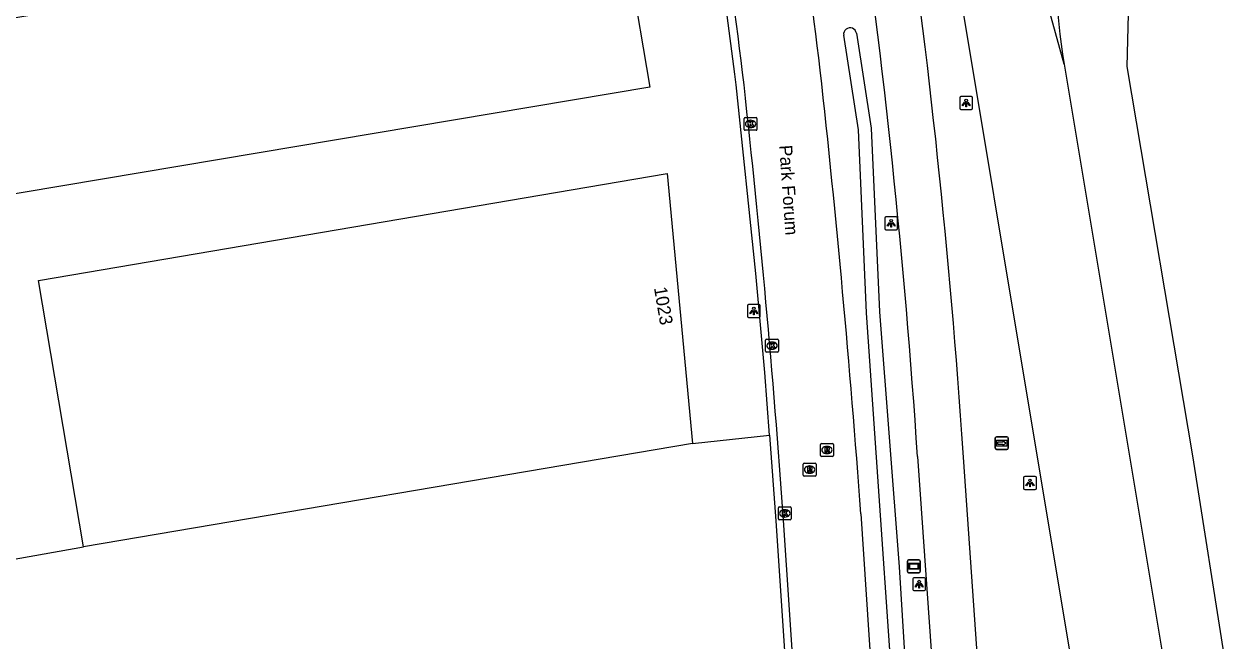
# Model space of a CAD drawing. Extents: x 154324 to 155743, y 382939 to 384183.
# Drawn here: x 155008 to 155101.4, y 383380.6 to 383428.3 of the extents above; entities that cross this region are included whole.
import ezdxf

# ---------------------------------------------------------------- set-up
doc = ezdxf.new("R2010")
doc.units = 0
for name, color, linetype in [('IMGEO_Fietspad_gesloten', 7, 'Continuous'), ('IMGEO_Grasland_agrarisch', 7, 'Continuous'), ('IMGEO_Greppel_droge_sloot', 7, 'Continuous'), ('IMGEO_Kolk', 7, 'Continuous'), ('IMGEO_Lichtpunt', 7, 'Continuous'), ('IMGEO_Loofbos', 7, 'Continuous'), ('IMGEO_Openbare_ruimte_label', 7, 'Continuous'), ('IMGEO_Pand', 7, 'Continuous'), ('IMGEO_Pand_nummerreeks', 7, 'Continuous'), ('IMGEO_Rijbaan_lokaal_gesloten', 7, 'Continuous'), ('IMGEO_Rijbaan_lokaal_open', 7, 'Continuous'), ('IMGEO_Rijbaan_regionaal_gesloten', 7, 'Continuous'), ('IMGEO_Rioolput', 7, 'Continuous'), ('IMGEO_Verklikker', 7, 'Continuous'), ('IMGEO_Wegwijzer', 7, 'Continuous')]:
    doc.layers.add(name, color=color, linetype=linetype)

msp = doc.modelspace()

# ---------------------------------------------------------------- linework, layer by layer
at = {"layer": 'IMGEO_Fietspad_gesloten'}
for points in [[(155077.17, 383394.842), (155080.905, 383341.835), (155081.566, 383327.494), (155081.827, 383312.283), (155081.9, 383290.584)], [(155085.135, 383323.941), (155085.067, 383327.696), (155084.447, 383341.596), (155080.698, 383395.149)]]:
    msp.add_lwpolyline(points, dxfattribs=at)
for centre, radius, start, end in [((154487.454, 383355.336), 594.578, 3.839363, 8.252921), ((154487.732, 383355.709), 590.736, 3.798282, 8.215646)]:
    msp.add_arc(centre, radius, start, end, dxfattribs=at)
at = {"layer": 'IMGEO_Grasland_agrarisch'}
for points in [[(154989.658, 383412.19), (154994.323, 383384.618), (155012.632, 383387.85)], [(155059.756, 383395.855), (155065.709, 383396.485)]]:
    msp.add_lwpolyline(points, dxfattribs=at)
at = {"layer": 'IMGEO_Greppel_droge_sloot'}
for points in [[(155076.041, 383365.341), (155073.219, 383405.951), (155072.594, 383420.096), (155071.455, 383427.398)], [(155072.443, 383427.552), (155073.586, 383420.223), (155074.216, 383406.02)], [(155074.216, 383406.02), (155075.741, 383386.313), (155077.04, 383365.403)]]:
    msp.add_lwpolyline(points, dxfattribs=at)
msp.add_arc((155071.949, 383427.475), 0.5, 8.85254, 188.86632, dxfattribs=at)
at = {"layer": 'IMGEO_Kolk'}
for p, q in [((155063.742, 383420.127), (155063.742, 383420.979)), ((155063.817, 383421.053), (155064.669, 383421.053)), ((155064.23, 383420.833), (155064.255, 383420.833)), ((155064.743, 383420.979), (155064.743, 383420.127)), ((155064.669, 383420.053), (155063.817, 383420.053)), ((155064.253, 383420.273), (155064.228, 383420.273)), ((155065.406, 383402.98), (155065.406, 383403.832)), ((155065.481, 383403.906), (155066.333, 383403.906)), ((155066.407, 383403.832), (155066.407, 383402.98)), ((155066.333, 383402.906), (155065.481, 383402.906)), ((155065.917, 383403.126), (155065.892, 383403.126)), ((155065.894, 383403.686), (155065.919, 383403.686)), ((155066.397, 383390.012), (155066.397, 383390.864)), ((155066.472, 383390.938), (155067.324, 383390.938)), ((155066.885, 383390.718), (155066.91, 383390.718)), ((155067.398, 383390.864), (155067.398, 383390.012)), ((155067.324, 383389.938), (155066.472, 383389.938)), ((155066.908, 383390.158), (155066.883, 383390.158))]:
    msp.add_line(p, q, dxfattribs=at)
for points in [[(155063.742, 383420.127), (155063.742, 383420.979)], [(155063.817, 383421.053), (155064.669, 383421.053)], [(155064.063, 383420.753), (155064.186, 383420.753), (155064.186, 383420.602), (155064.316, 383420.753), (155064.48, 383420.753), (155064.334, 383420.602), (155064.487, 383420.353), (155064.335, 383420.353), (155064.25, 383420.517), (155064.186, 383420.45), (155064.186, 383420.353), (155064.063, 383420.353), (155064.063, 383420.753)], [(155064.743, 383420.979), (155064.743, 383420.127)], [(155064.669, 383420.053), (155063.817, 383420.053)], [(155065.406, 383402.98), (155065.406, 383403.832)], [(155065.481, 383403.906), (155066.333, 383403.906)], [(155066.407, 383403.832), (155066.407, 383402.98)], [(155066.333, 383402.906), (155065.481, 383402.906)], [(155065.727, 383403.606), (155065.85, 383403.606), (155065.85, 383403.455), (155065.98, 383403.606), (155066.144, 383403.606), (155065.998, 383403.455), (155066.151, 383403.206), (155065.999, 383403.206), (155065.914, 383403.37), (155065.85, 383403.303), (155065.85, 383403.206), (155065.727, 383403.206), (155065.727, 383403.606)], [(155066.397, 383390.012), (155066.397, 383390.864)], [(155066.472, 383390.938), (155067.324, 383390.938)], [(155067.398, 383390.864), (155067.398, 383390.012)], [(155067.324, 383389.938), (155066.472, 383389.938)], [(155066.718, 383390.638), (155066.841, 383390.638), (155066.841, 383390.487), (155066.971, 383390.638), (155067.135, 383390.638), (155066.989, 383390.487), (155067.142, 383390.238), (155066.99, 383390.238), (155066.905, 383390.402), (155066.841, 383390.335), (155066.841, 383390.238), (155066.718, 383390.238), (155066.718, 383390.638)]]:
    msp.add_lwpolyline(points, dxfattribs=at)
for centre, start, end in [((155063.819, 383420.977), 91.55205, 178.44795), ((155063.819, 383420.977), 91.55205, 178.44795), ((155064.667, 383420.977), 1.55205, 88.44795), ((155064.667, 383420.977), 1.55205, 88.44795), ((155063.819, 383420.129), 181.55205, 268.44795), ((155063.819, 383420.129), 181.55205, 268.44795), ((155064.667, 383420.129), 271.55205, 358.44795), ((155064.667, 383420.129), 271.55205, 358.44795), ((155065.483, 383403.83), 91.55205, 178.44795), ((155065.483, 383403.83), 91.55205, 178.44795), ((155066.331, 383403.83), 1.55205, 88.44795), ((155066.331, 383403.83), 1.55205, 88.44795), ((155065.483, 383402.982), 181.55205, 268.44795), ((155065.483, 383402.982), 181.55205, 268.44795), ((155066.331, 383402.982), 271.55205, 358.44795), ((155066.331, 383402.982), 271.55205, 358.44795), ((155066.474, 383390.862), 91.55205, 178.44795), ((155066.474, 383390.862), 91.55205, 178.44795), ((155067.322, 383390.862), 1.55205, 88.44795), ((155067.322, 383390.862), 1.55205, 88.44795), ((155066.474, 383390.014), 181.55205, 268.44795), ((155066.474, 383390.014), 181.55205, 268.44795), ((155067.322, 383390.014), 271.55205, 358.44795), ((155067.322, 383390.014), 271.55205, 358.44795)]:
    msp.add_arc(centre, 0.0765, start, end, dxfattribs=at)
for centre, major_axis, ratio, start_param, end_param in [((155064.229, 383420.553), (-0.387, 0.002), 0.722429, 4.712389, 7.853982), ((155064.254, 383420.553), (-0.39, 0.002), 0.717154, 1.570796, 4.712389), ((155065.893, 383403.406), (-0.387, 0.002), 0.722429, 4.712389, 7.853982), ((155065.918, 383403.406), (-0.39, 0.002), 0.717154, 1.570796, 4.712389), ((155066.884, 383390.438), (-0.387, 0.002), 0.722429, 4.712389, 7.853982), ((155066.909, 383390.438), (-0.39, 0.002), 0.717154, 1.570796, 4.712389)]:
    msp.add_ellipse(centre, major_axis=major_axis, ratio=ratio, start_param=start_param, end_param=end_param, dxfattribs=at)
at = {"layer": 'IMGEO_Lichtpunt'}
for p, q in [((155080.434, 383422.566), (155080.434, 383421.759)), ((155080.434, 383422.566), (155080.434, 383421.759)), ((155081.336, 383422.661), (155080.528, 383422.661)), ((155081.336, 383422.661), (155080.528, 383422.661)), ((155081.43, 383421.759), (155081.43, 383422.566)), ((155081.43, 383421.759), (155081.43, 383422.566)), ((155080.528, 383421.665), (155081.336, 383421.665)), ((155080.528, 383421.665), (155081.336, 383421.665)), ((155074.633, 383413.273), (155074.633, 383412.466)), ((155074.633, 383413.273), (155074.633, 383412.466)), ((155075.535, 383413.368), (155074.727, 383413.368)), ((155075.535, 383413.368), (155074.727, 383413.368)), ((155075.629, 383412.466), (155075.629, 383413.273)), ((155075.629, 383412.466), (155075.629, 383413.273)), ((155074.727, 383412.372), (155075.535, 383412.372)), ((155074.727, 383412.372), (155075.535, 383412.372)), ((155064.902, 383406.59), (155064.094, 383406.59)), ((155064.902, 383406.59), (155064.094, 383406.59)), ((155064, 383406.495), (155064, 383405.688)), ((155064, 383406.495), (155064, 383405.688)), ((155064.094, 383405.594), (155064.902, 383405.594)), ((155064.094, 383405.594), (155064.902, 383405.594)), ((155064.996, 383405.688), (155064.996, 383406.495)), ((155064.996, 383405.688), (155064.996, 383406.495)), ((155085.373, 383393.191), (155085.373, 383392.384)), ((155085.373, 383393.191), (155085.373, 383392.384)), ((155086.275, 383393.286), (155085.467, 383393.286)), ((155086.275, 383393.286), (155085.467, 383393.286)), ((155086.369, 383392.384), (155086.369, 383393.191)), ((155086.369, 383392.384), (155086.369, 383393.191)), ((155085.467, 383392.29), (155086.275, 383392.29)), ((155085.467, 383392.29), (155086.275, 383392.29)), ((155076.799, 383385.371), (155076.799, 383384.564)), ((155076.799, 383385.371), (155076.799, 383384.564)), ((155077.701, 383385.466), (155076.893, 383385.466)), ((155077.701, 383385.466), (155076.893, 383385.466)), ((155077.795, 383384.564), (155077.795, 383385.371)), ((155077.795, 383384.564), (155077.795, 383385.371)), ((155076.893, 383384.47), (155077.701, 383384.47)), ((155076.893, 383384.47), (155077.701, 383384.47))]:
    msp.add_line(p, q, dxfattribs=at)
for points in [[(155080.808, 383422.23), (155080.847, 383422.202), (155080.659, 383421.94), (155080.621, 383421.967), (155080.808, 383422.23)], [(155080.91, 383422.182), (155080.957, 383422.182), (155080.957, 383421.86), (155080.91, 383421.86), (155080.91, 383422.182)], [(155081.02, 383422.202), (155081.058, 383422.229), (155081.245, 383421.967), (155081.206, 383421.939), (155081.02, 383422.202)], [(155075.007, 383412.937), (155075.046, 383412.909), (155074.858, 383412.647), (155074.82, 383412.674), (155075.007, 383412.937)], [(155075.109, 383412.889), (155075.156, 383412.889), (155075.156, 383412.567), (155075.109, 383412.567), (155075.109, 383412.889)], [(155075.219, 383412.909), (155075.257, 383412.936), (155075.444, 383412.674), (155075.405, 383412.646), (155075.219, 383412.909)], [(155064.374, 383406.159), (155064.413, 383406.131), (155064.225, 383405.869), (155064.187, 383405.896), (155064.374, 383406.159)], [(155064.476, 383406.111), (155064.523, 383406.111), (155064.523, 383405.789), (155064.476, 383405.789), (155064.476, 383406.111)], [(155064.586, 383406.131), (155064.624, 383406.158), (155064.811, 383405.896), (155064.772, 383405.868), (155064.586, 383406.131)], [(155085.747, 383392.855), (155085.786, 383392.827), (155085.598, 383392.565), (155085.56, 383392.592), (155085.747, 383392.855)], [(155085.849, 383392.807), (155085.896, 383392.807), (155085.896, 383392.485), (155085.849, 383392.485), (155085.849, 383392.807)], [(155085.959, 383392.827), (155085.997, 383392.854), (155086.184, 383392.592), (155086.145, 383392.564), (155085.959, 383392.827)], [(155077.173, 383385.035), (155077.212, 383385.007), (155077.024, 383384.745), (155076.986, 383384.772), (155077.173, 383385.035)], [(155077.275, 383384.987), (155077.322, 383384.987), (155077.322, 383384.665), (155077.275, 383384.665), (155077.275, 383384.987)], [(155077.385, 383385.007), (155077.423, 383385.034), (155077.61, 383384.772), (155077.571, 383384.744), (155077.385, 383385.007)]]:
    msp.add_lwpolyline(points, dxfattribs=at)
for centre in [(155080.933, 383422.364), (155075.132, 383413.071), (155064.499, 383406.293), (155085.872, 383392.989), (155077.298, 383385.169)]:
    msp.add_circle(centre, 0.0994, dxfattribs=at)
for centre, start, end in [((155080.528, 383422.566), 90, 180), ((155080.528, 383422.566), 90, 180), ((155081.336, 383422.566), 0, 90), ((155081.336, 383422.566), 0, 90), ((155080.528, 383421.759), 180, 270), ((155080.528, 383421.759), 180, 270), ((155081.336, 383421.759), 270, 0), ((155081.336, 383421.759), 270, 360), ((155074.727, 383413.273), 90, 180), ((155074.727, 383413.273), 90, 180), ((155075.535, 383413.273), 0, 90), ((155075.535, 383413.273), 0, 90), ((155074.727, 383412.466), 180, 270), ((155074.727, 383412.466), 180, 270), ((155075.535, 383412.466), 270, 0), ((155075.535, 383412.466), 270, 360), ((155064.094, 383406.495), 90, 180), ((155064.094, 383406.495), 90, 180), ((155064.902, 383406.495), 0, 90), ((155064.902, 383406.495), 0, 90), ((155064.094, 383405.688), 180, 270), ((155064.094, 383405.688), 180, 270), ((155064.902, 383405.688), 270, 0), ((155064.902, 383405.688), 270, 360), ((155085.467, 383393.191), 90, 180), ((155085.467, 383393.191), 90, 180), ((155086.275, 383393.191), 0, 90), ((155086.275, 383393.191), 0, 90), ((155085.467, 383392.384), 180, 270), ((155085.467, 383392.384), 180, 270), ((155086.275, 383392.384), 270, 0), ((155086.275, 383392.384), 270, 360), ((155076.893, 383385.371), 90, 180), ((155076.893, 383385.371), 90, 180), ((155077.701, 383385.371), 0, 90), ((155077.701, 383385.371), 0, 90), ((155076.893, 383384.564), 180, 270), ((155076.893, 383384.564), 180, 270), ((155077.701, 383384.564), 270, 0), ((155077.701, 383384.564), 270, 360)]:
    msp.add_arc(centre, 0.0946, start, end, dxfattribs=at)
at = {"layer": 'IMGEO_Loofbos'}
msp.add_lwpolyline([(155098.468, 383394.88), (155093.402, 383424.985), (155093.91, 383445.3), (155100.943, 383462.488), (155107.736, 383471.089), (155129.143, 383483.74), (155137.144, 383484.281), (155140.63, 383467.071), (155136.381, 383463.412), (155137.911, 383457.313), (155135.315, 383439.71), (155145.951, 383434.989), (155156.14, 383427.969), (155169.731, 383420.841), (155156.553, 383398.835), (155144.405, 383376.88), (155136.829, 383369.749), (155130.45, 383360.745), (155130.039, 383352.225), (155124.389, 383342.473), (155103.488, 383363.139), (155098.468, 383394.88)], dxfattribs=at)
at = {"layer": 'IMGEO_Pand'}
for points in [[(154987.442, 383425.439), (155016.017, 383430.255), (155015.086, 383435.797), (155040.407, 383440.106), (155045.605, 383440.97), (155045.151, 383443.703), (155044.599, 383443.611), (155044.545, 383443.936), (155052.777, 383445.305), (155054.28, 383436.31), (155053.008, 383436.097), (155053.665, 383432.17), (155054.937, 383432.384), (155056.445, 383423.395), (154989.658, 383412.19)], [(155012.632, 383387.85), (155009.132, 383408.441), (155057.795, 383416.713), (155059.756, 383395.855)], [(155059.756, 383395.855), (155012.632, 383387.85)]]:
    msp.add_lwpolyline(points, dxfattribs=at)
at = {"layer": 'IMGEO_Rijbaan_lokaal_gesloten'}
for points in [[(155070.546, 383334.082), (155066.805, 383389.917)], [(155072.788, 383390.399), (155076.503, 383334.279)]]:
    msp.add_lwpolyline(points, dxfattribs=at)
for centre, radius, start, end in [((154416.191, 383345.471), 658.237, 6.914298, 9.527814), ((154372.74, 383339.354), 696.116, 6.949521, 9.434678), ((154136.569, 383321.838), 938.726, 4.1884, 6.291685), ((154201.434, 383328.122), 867.574, 4.08448, 6.316961)]:
    msp.add_arc(centre, radius, start, end, dxfattribs=at)
at = {"layer": 'IMGEO_Rijbaan_lokaal_open'}
for points in [[(155065.709, 383396.485), (155065.341, 383401.33), (155064.659, 383408.986), (155063.139, 383423.564), (155063.03, 383424.403), (155061.613, 383435.27), (155060.487, 383443.041), (155058.846, 383453.397), (155045.918, 383530.449), (155024.164, 383660.104), (155016.277, 383707.107)], [(155065.709, 383396.485), (155066.213, 383389.857), (155069.432, 383341.538), (155069.458, 383341.15)]]:
    msp.add_lwpolyline(points, dxfattribs=at)
at = {"layer": 'IMGEO_Rijbaan_regionaal_gesloten'}
for points in [[(155071.187, 383485.369), (155076.819, 383452.367), (155095.519, 383340.332), (155097.848, 383325.634)], [(155088.506, 383425.158), (155082.147, 383448.215)], [(155088.506, 383425.158), (155097.016, 383374.301)]]:
    msp.add_lwpolyline(points, dxfattribs=at)
msp.add_arc((155150.9, 383434.774), 63.13, 166.13008, 188.76182, dxfattribs=at)
at = {"layer": 'IMGEO_Rioolput'}
for p, q in [((155069.656, 383394.918), (155069.656, 383395.77)), ((155069.731, 383395.844), (155070.583, 383395.844)), ((155070.144, 383395.624), (155070.169, 383395.624)), ((155070.657, 383395.77), (155070.657, 383394.918)), ((155070.583, 383394.844), (155069.731, 383394.844)), ((155070.167, 383395.064), (155070.142, 383395.064)), ((155068.313, 383393.402), (155068.313, 383394.254)), ((155068.388, 383394.328), (155069.24, 383394.328)), ((155068.824, 383393.548), (155068.799, 383393.548)), ((155068.801, 383394.108), (155068.826, 383394.108)), ((155069.314, 383394.254), (155069.314, 383393.402)), ((155069.24, 383393.328), (155068.388, 383393.328))]:
    msp.add_line(p, q, dxfattribs=at)
for points in [[(155069.656, 383394.918), (155069.656, 383395.77)], [(155069.731, 383395.844), (155070.583, 383395.844)], [(155070.245, 383395.542), (155069.993, 383395.544), (155069.993, 383395.144)], [(155070.171, 383395.463), (155070.117, 383395.463), (155070.117, 383395.382)], [(155070.117, 383395.382), (155070.169, 383395.382)], [(155070.657, 383395.77), (155070.657, 383394.918)], [(155070.583, 383394.844), (155069.731, 383394.844)], [(155069.993, 383395.144), (155070.117, 383395.144), (155070.117, 383395.306), (155070.128, 383395.306)], [(155070.175, 383395.277), (155070.246, 383395.144), (155070.386, 383395.144), (155070.321, 383395.27)], [(155068.313, 383393.402), (155068.313, 383394.254)], [(155068.388, 383394.328), (155069.24, 383394.328)], [(155068.902, 383394.026), (155068.65, 383394.028), (155068.65, 383393.628)], [(155068.65, 383393.628), (155068.774, 383393.628), (155068.774, 383393.79), (155068.785, 383393.79)], [(155068.828, 383393.947), (155068.774, 383393.947), (155068.774, 383393.866)], [(155068.774, 383393.866), (155068.826, 383393.866)], [(155068.832, 383393.761), (155068.903, 383393.628), (155069.043, 383393.628), (155068.978, 383393.754)], [(155069.314, 383394.254), (155069.314, 383393.402)], [(155069.24, 383393.328), (155068.388, 383393.328)]]:
    msp.add_lwpolyline(points, dxfattribs=at)
for centre, radius, start, end in [((155069.733, 383395.768), 0.0765, 91.55205, 178.44795), ((155069.733, 383395.768), 0.0765, 91.55205, 178.44795), ((155070.153, 383395.571), 0.19, 274.7715, 282.96867), ((155070.177, 383395.367), 0.0964, 77.00612, 93.18647), ((155070.191, 383395.424), 0.0378, 276.66336, 79.67722), ((155070.244, 383395.432), 0.109, 350.36119, 89.41601), ((155070.242, 383395.432), 0.112, 277.58423, 350.98172), ((155070.226, 383395.217), 0.108, 29.51342, 73.79051), ((155070.581, 383395.768), 0.0765, 1.55205, 88.44795), ((155070.581, 383395.768), 0.0765, 1.55205, 88.44795), ((155069.733, 383394.92), 0.0765, 181.55205, 268.44795), ((155069.733, 383394.92), 0.0765, 181.55205, 268.44795), ((155070.127, 383395.253), 0.0533, 26.02933, 88.69889), ((155070.581, 383394.92), 0.0765, 271.55205, 358.44795), ((155070.581, 383394.92), 0.0765, 271.55205, 358.44795), ((155068.39, 383394.252), 0.0765, 91.55205, 178.44795), ((155068.39, 383394.252), 0.0765, 91.55205, 178.44795), ((155068.784, 383393.737), 0.0533, 26.02933, 88.69889), ((155068.81, 383394.055), 0.19, 274.7715, 282.96867), ((155068.834, 383393.851), 0.0964, 77.00612, 93.18647), ((155068.848, 383393.908), 0.0378, 276.66336, 79.67722), ((155068.901, 383393.916), 0.109, 350.36119, 89.41601), ((155068.899, 383393.916), 0.112, 277.58423, 350.98172), ((155068.883, 383393.701), 0.108, 29.51342, 73.79051), ((155069.238, 383394.252), 0.0765, 1.55205, 88.44795), ((155069.238, 383394.252), 0.0765, 1.55205, 88.44795), ((155068.39, 383393.404), 0.0765, 181.55205, 268.44795), ((155068.39, 383393.404), 0.0765, 181.55205, 268.44795), ((155069.238, 383393.404), 0.0765, 271.55205, 358.44795), ((155069.238, 383393.404), 0.0765, 271.55205, 358.44795)]:
    msp.add_arc(centre, radius, start, end, dxfattribs=at)
for centre, major_axis, ratio, start_param, end_param in [((155070.143, 383395.344), (-0.387, 0.002), 0.722429, 4.712389, 7.853982), ((155070.168, 383395.344), (-0.39, 0.002), 0.717154, 1.570796, 4.712389), ((155068.8, 383393.828), (-0.387, 0.002), 0.722429, 4.712389, 7.853982), ((155068.825, 383393.828), (-0.39, 0.002), 0.717154, 1.570796, 4.712389)]:
    msp.add_ellipse(centre, major_axis=major_axis, ratio=ratio, start_param=start_param, end_param=end_param, dxfattribs=at)
at = {"layer": 'IMGEO_Verklikker'}
for p, q in [((155076.382, 383385.953), (155076.382, 383386.753)), ((155076.382, 383386.753), (155076.382, 383385.953)), ((155076.482, 383386.853), (155077.272, 383386.853)), ((155077.272, 383386.853), (155076.482, 383386.853)), ((155077.372, 383386.753), (155077.372, 383385.953)), ((155077.372, 383385.953), (155077.372, 383386.753)), ((155077.272, 383385.853), (155076.482, 383385.853)), ((155076.482, 383385.853), (155077.272, 383385.853))]:
    msp.add_line(p, q, dxfattribs=at)
for points in [[(155076.483, 383386.585), (155077.271, 383386.585), (155077.271, 383386.121), (155076.483, 383386.121), (155076.483, 383386.585)], [(155076.548, 383386.52), (155076.548, 383386.186), (155077.206, 383386.186), (155077.206, 383386.52), (155076.548, 383386.52)]]:
    msp.add_lwpolyline(points, dxfattribs=at)
for centre, start, end in [((155076.482, 383386.753), 90, 180), ((155076.482, 383386.753), 90, 180), ((155077.272, 383386.753), 0, 90), ((155077.272, 383386.753), 360, 90), ((155076.482, 383385.953), 180, 270), ((155076.482, 383385.953), 180, 270), ((155077.272, 383385.953), 270, 0), ((155077.272, 383385.953), 270, 0)]:
    msp.add_arc(centre, 0.1, start, end, dxfattribs=at)
at = {"layer": 'IMGEO_Wegwijzer'}
for p, q in [((155083.188, 383395.471), (155083.188, 383396.271)), ((155083.188, 383396.271), (155083.188, 383395.471)), ((155083.288, 383396.371), (155084.078, 383396.371)), ((155084.078, 383396.371), (155083.288, 383396.371)), ((155084.178, 383396.271), (155084.178, 383395.471)), ((155084.178, 383395.471), (155084.178, 383396.271)), ((155084.078, 383395.371), (155083.288, 383395.371)), ((155083.288, 383395.371), (155084.078, 383395.371))]:
    msp.add_line(p, q, dxfattribs=at)
for points in [[(155083.289, 383396.103), (155084.077, 383396.103), (155084.077, 383395.639), (155083.289, 383395.639), (155083.289, 383396.103)], [(155083.354, 383395.955), (155083.354, 383395.871), (155083.354, 383395.787), (155083.765, 383395.787), (155083.765, 383395.704), (155084.012, 383395.871), (155083.765, 383396.038), (155083.765, 383395.955), (155083.354, 383395.955)]]:
    msp.add_lwpolyline(points, dxfattribs=at)
for centre, start, end in [((155083.288, 383396.271), 90, 180), ((155083.288, 383396.271), 90, 180), ((155084.078, 383396.271), 0, 90), ((155084.078, 383396.271), 360, 90), ((155083.288, 383395.471), 180, 270), ((155083.288, 383395.471), 180, 270), ((155084.078, 383395.471), 270, 0), ((155084.078, 383395.471), 270, 0)]:
    msp.add_arc(centre, 0.1, start, end, dxfattribs=at)

# ---------------------------------------------------------------- texts
at = {"layer": 'IMGEO_Openbare_ruimte_label'}
msp.add_text('Park Forum', height=1, rotation=274.01217, dxfattribs=at).set_placement((155066.461, 383418.881))
at = {"layer": 'IMGEO_Pand_nummerreeks'}
msp.add_text('1023', height=1, rotation=279.64267, dxfattribs=at).set_placement((155056.768, 383407.874))

doc.saveas('drawing.dxf')
